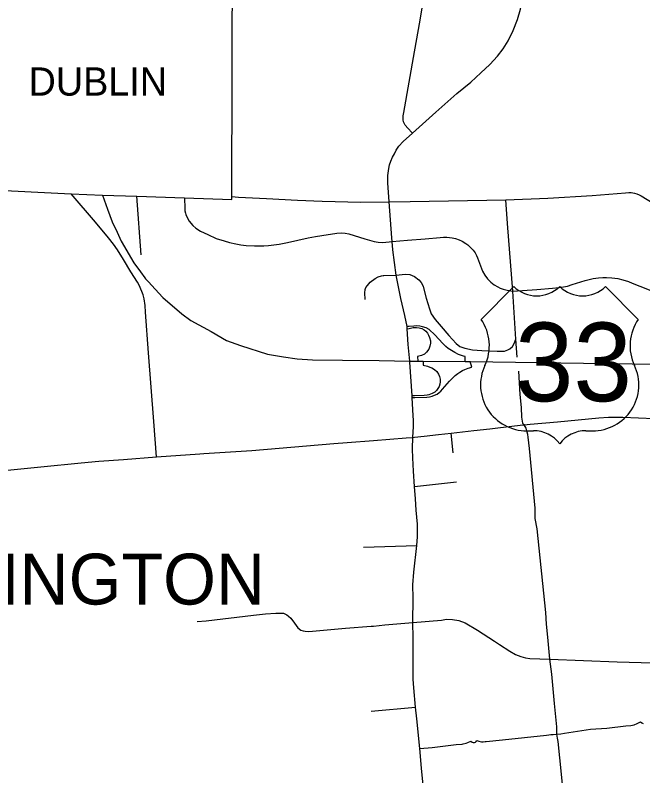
# Model space of a CAD drawing. Extents: x 1755200 to 1902939, y 644115 to 788070.
# Drawn here: x 1777186 to 1788296, y 757899 to 771361 of the extents above; entities that cross this region are included whole.
import ezdxf

# ---------------------------------------------------------------- set-up
doc = ezdxf.new("R2010")
doc.units = 0
for name, color, linetype in [('GM_X_City_Street', 7, 'Continuous'), ('GM_X_Corporation_Text', 7, 'Continuous'), ('GM_X_County', 7, 'Continuous'), ('GM_X_County_Road', 7, 'Continuous'), ('GM_X_Interchange_Ramps', 7, 'Continuous'), ('GM_X_Township_Text', 7, 'Continuous'), ('GM_X_US_Route', 7, 'Continuous'), ('GM_X_US_Shield', 7, 'Continuous')]:
    doc.layers.add(name, color=color, linetype=linetype)

msp = doc.modelspace()

# ---------------------------------------------------------------- linework, layer by layer
at = {"layer": 'GM_X_City_Street'}
for points in [[(1784219, 769275), (1784630, 769643), (1785003, 769974), (1785250, 770175), (1785431, 770342), (1785586, 770486), (1785725, 770636), (1785822, 770764), (1785915, 770909), (1786003, 771088), (1786080, 771284), (1786130, 771467), (1786180, 771733), (1786271, 772205), (1786359, 772769), (1786375, 772928), (1786368, 773096), (1786350, 773256), (1786330, 773355)], [(1784213, 769281), (1784139, 769359), (1784090, 769415), (1784062, 769474), (1784054, 769512), (1784054, 769579), (1784065, 769640), (1784254, 770715), (1784357, 771275), (1784523, 772309), (1784617, 772879)], [(1783804, 768056), (1783780, 768394), (1783780, 768450), (1783783, 768525), (1783798, 768648), (1783813, 768714), (1783836, 768775), (1783866, 768846), (1783898, 768910), (1783928, 768970), (1783978, 769042), (1784055, 769126), (1784219, 769275), (1784213, 769281)], [(1779493, 766103), (1779484, 766221), (1779471, 766340), (1779453, 766411), (1779385, 766572), (1779352, 766635), (1779235, 766821), (1779105, 767038), (1778997, 767211), (1778926, 767307), (1778839, 767419), (1778606, 767697), (1778179, 768197)], [(1781021, 768152), (1781136, 768138), (1781634, 768114), (1782186, 768090), (1782622, 768070), (1783303, 768053), (1783804, 768056), (1784178, 768065), (1785871, 768094), (1786614, 768122), (1787402, 768168), (1787989, 768220), (1788050, 768225), (1788088, 768222), (1788147, 768214), (1788188, 768200), (1788232, 768182), (1788269, 768163), (1789144, 767627)], [(1779414, 767119), (1779340, 768157)], [(1780182, 768130), (1780186, 767940), (1780191, 767900), (1780199, 767860), (1780209, 767831), (1780225, 767791), (1780264, 767716), (1780328, 767640), (1780383, 767593), (1780464, 767541), (1780593, 767477), (1780746, 767411), (1780882, 767365), (1780980, 767338), (1781089, 767315), (1781178, 767298), (1781275, 767287), (1781420, 767277), (1781586, 767278), (1781671, 767283), (1781767, 767294), (1781857, 767309), (1782004, 767339), (1782372, 767420), (1782502, 767447), (1782613, 767464), (1782882, 767503), (1782970, 767511), (1783029, 767506), (1783091, 767492), (1783376, 767405), (1783539, 767357), (1783614, 767345), (1783692, 767340), (1783857, 767355)], [(1783852, 767420), (1783804, 768056)], [(1786072, 765306), (1786049, 765627), (1785994, 766475), (1785901, 767676), (1785871, 768094)], [(1784124, 765809), (1784124, 765849), (1784086, 766044), (1784010, 766349), (1783927, 766762), (1783870, 767211), (1783857, 767355), (1783852, 767420)], [(1783857, 767355), (1784133, 767378), (1784442, 767403), (1784707, 767426), (1784770, 767430), (1784829, 767433), (1784875, 767429), (1784924, 767421), (1784983, 767408), (1785048, 767383), (1785097, 767361), (1785164, 767319), (1785196, 767295), (1785235, 767263), (1785294, 767200), (1785327, 767154), (1785353, 767109), (1785372, 767066), (1785457, 766832), (1785497, 766760), (1785547, 766692), (1785604, 766637), (1785664, 766590), (1785727, 766554), (1785772, 766532), (1785825, 766512), (1785893, 766493), (1785994, 766475)], [(1783380, 766332), (1783377, 766447), (1783380, 766504), (1783395, 766540), (1783423, 766579), (1783467, 766638), (1783560, 766703), (1783610, 766729), (1783668, 766747), (1783699, 766752)], [(1783699, 766752), (1783711, 766754), (1783927, 766762)], [(1783927, 766762), (1784087, 766780), (1784169, 766769), (1784254, 766735), (1784329, 766680), (1784371, 766630)], [(1785994, 766475), (1786422, 766506), (1786697, 766528), (1786810, 766539), (1786893, 766552), (1786966, 766568), (1787044, 766592), (1787277, 766667), (1787418, 766703), (1787513, 766714), (1787587, 766718), (1787656, 766721), (1787746, 766714), (1787852, 766701), (1787940, 766680), (1788043, 766647), (1788107, 766621), (1788242, 766568), (1788469, 766478)], [(1784371, 766630), (1784376, 766624), (1784408, 766561), (1784463, 766354), (1784518, 766165), (1784550, 766075), (1784618, 765975), (1784726, 765853), (1784860, 765691), (1784992, 765549), (1785058, 765499), (1785146, 765465), (1785280, 765436), (1785444, 765424), (1785717, 765413), (1785849, 765415), (1785906, 765439), (1785943, 765457), (1785988, 765495), (1786021, 765551), (1786049, 765627)], [(1779685, 763542), (1779637, 764172), (1779545, 765387), (1779493, 766103)], [(1784171, 765217), (1784170, 765235), (1784144, 765530), (1784124, 765809)], [(1784233, 764269), (1784215, 764596), (1784214, 764625), (1784171, 765217)], [(1786194, 764108), (1786181, 764123), (1786174, 764142), (1786157, 764248), (1786146, 764419), (1786127, 764649), (1786100, 765059)], [(1784229, 763410), (1784229, 763419), (1784225, 763513), (1784220, 763690), (1784225, 763888), (1784235, 764083), (1784237, 764194), (1784233, 764269)], [(1786194, 764108), (1786301, 764120), (1786784, 764165), (1787517, 764236), (1787687, 764247), (1787940, 764244), (1788496, 764220), (1788942, 764207)], [(1784256, 763891), (1784428, 763910), (1784682, 763942), (1784901, 763964), (1785303, 764011), (1785590, 764041), (1785732, 764058), (1786128, 764102), (1786194, 764108)], [(1786891, 757566), (1786854, 757927), (1786800, 758507), (1786789, 758566), (1786774, 758633), (1786775, 758765), (1786733, 759178), (1786683, 759695), (1786650, 759962), (1786616, 760352), (1786592, 760584), (1786580, 760788), (1786424, 762272), (1786390, 762450), (1786389, 762635), (1786289, 763689), (1786266, 763891), (1786259, 763942), (1786246, 764003), (1786230, 764049), (1786194, 764108)], [(1780526, 763602), (1781375, 763657), (1782825, 763782), (1783060, 763799), (1783527, 763834), (1784109, 763878), (1784225, 763888), (1784256, 763891)], [(1784937, 763614), (1784901, 763964)], [(1779104, 763498), (1779685, 763542), (1780457, 763598), (1780526, 763602)], [(1784431, 757489), (1784381, 758034), (1784347, 758381), (1784296, 758904), (1784274, 759116), (1784240, 759453), (1784230, 759608), (1784232, 759677), (1784229, 760052), (1784230, 760338), (1784227, 760609), (1784231, 761045), (1784227, 761277), (1784240, 761501), (1784293, 761975), (1784305, 762129), (1784308, 762257), (1784306, 762353), (1784284, 762601), (1784271, 762802), (1784255, 763022), (1784234, 763291), (1784229, 763410)], [(1784255, 763022), (1784997, 763101)], [(1783351, 761947), (1784293, 761975)], [(1781403, 760741), (1781614, 760766), (1781798, 760777), (1781933, 760777), (1781997, 760747), (1782023, 760726)], [(1780404, 760630), (1780564, 760644), (1781403, 760741)], [(1782023, 760726), (1782065, 760691), (1782129, 760598), (1782192, 760517), (1782245, 760477), (1782283, 760463), (1782319, 760456), (1782381, 760453)], [(1784227, 760609), (1784735, 760656), (1784822, 760669), (1784927, 760665), (1785037, 760648), (1785151, 760606), (1785370, 760479), (1785672, 760283), (1785762, 760223), (1785944, 760103), (1786045, 760047), (1786138, 760011), (1786218, 759985), (1786298, 759975), (1786650, 759962), (1787842, 759914), (1788482, 759895)], [(1782381, 760453), (1782386, 760453), (1783031, 760512), (1783489, 760546)], [(1783489, 760546), (1783531, 760549), (1783727, 760569), (1784227, 760609)], [(1783488, 759043), (1784274, 759116)], [(1785443, 758502), (1785447, 758501), (1785472, 758500), (1785504, 758503), (1785525, 758504), (1785812, 758536), (1786594, 758619), (1786632, 758624), (1786670, 758627), (1786708, 758629), (1786774, 758633), (1786846, 758644), (1786908, 758654), (1787368, 758722), (1787661, 758743), (1787994, 758780), (1788083, 758790), (1788142, 758802), (1788198, 758823), (1788258, 758854), (1788279, 758834), (1788304, 758825)], [(1785099, 758461), (1785117, 758463), (1785168, 758475), (1785196, 758486), (1785249, 758513), (1785274, 758493), (1785296, 758489), (1785314, 758489), (1785332, 758496), (1785348, 758508), (1785360, 758524), (1785395, 758514), (1785443, 758502)], [(1784347, 758381), (1784569, 758402), (1784992, 758452), (1785099, 758461)]]:
    msp.add_lwpolyline(points, dxfattribs=at)
at = {"layer": 'GM_X_County'}
msp.add_lwpolyline([(1775112, 768352), (1778179, 768197), (1778733, 768178), (1779340, 768157), (1780182, 768130), (1781021, 768101), (1781021, 768152), (1781038, 774723)], dxfattribs=at)
at = {"layer": 'GM_X_County_Road'}
msp.add_lwpolyline([(1776312, 763238), (1776864, 763293), (1777637, 763368), (1778352, 763436), (1778667, 763465), (1779104, 763498)], dxfattribs=at)
at = {"layer": 'GM_X_Interchange_Ramps'}
for points in [[(1785153, 765233), (1785154, 765320), (1785124, 765326), (1785036, 765358), (1784970, 765390), (1784907, 765424), (1784851, 765461), (1784810, 765495), (1784755, 765549), (1784613, 765705), (1784512, 765799), (1784462, 765826), (1784398, 765848), (1784348, 765859), (1784295, 765863), (1784240, 765858), (1784159, 765854), (1784124, 765849)], [(1784124, 765809), (1784161, 765815), (1784230, 765832), (1784292, 765836), (1784340, 765828), (1784382, 765814), (1784423, 765791), (1784453, 765767), (1784482, 765734), (1784505, 765698), (1784522, 765654), (1784536, 765596), (1784538, 765557), (1784528, 765501), (1784506, 765449), (1784469, 765398), (1784430, 765363), (1784381, 765338), (1784309, 765320), (1784313, 765239)], [(1784407, 765240), (1784406, 765164), (1784482, 765148), (1784524, 765134), (1784564, 765117), (1784608, 765091), (1784651, 765052), (1784680, 765010), (1784696, 764968), (1784709, 764918), (1784709, 764871), (1784702, 764833), (1784689, 764792), (1784670, 764756), (1784642, 764719), (1784614, 764691), (1784570, 764665), (1784539, 764652), (1784506, 764641), (1784479, 764636), (1784426, 764632), (1784254, 764626), (1784214, 764625)], [(1784215, 764596), (1784263, 764593), (1784470, 764602), (1784518, 764608), (1784567, 764617), (1784610, 764633), (1784654, 764656), (1784690, 764681), (1784722, 764709), (1784752, 764740), (1784875, 764884), (1784926, 764939), (1784976, 764983), (1785023, 765019), (1785056, 765043), (1785106, 765071), (1785147, 765091), (1785206, 765113), (1785270, 765131), (1785239, 765232)]]:
    msp.add_lwpolyline(points, dxfattribs=at)
at = {"layer": 'GM_X_US_Route'}
for points in [[(1778733, 768178), (1778817, 767930), (1778905, 767705), (1778988, 767518), (1779062, 767362), (1779287, 766981), (1779404, 766816), (1779481, 766710)], [(1779481, 766710), (1779494, 766693), (1779551, 766633)], [(1779551, 766633), (1779597, 766584), (1779797, 766367), (1780136, 766075), (1780293, 765955), (1780653, 765760), (1780928, 765603), (1781172, 765512), (1781651, 765359), (1781933, 765316), (1782177, 765280), (1782448, 765261), (1782979, 765256)], [(1782979, 765256), (1783630, 765249), (1784170, 765235)], [(1784170, 765235), (1784313, 765239), (1784407, 765240), (1785153, 765233), (1785239, 765232), (1787647, 765195), (1789027, 765180), (1789601, 765171), (1789778, 765169)]]:
    msp.add_lwpolyline(points, dxfattribs=at)
at = {"layer": 'GM_X_US_Shield'}
for p, q in [((1786013, 766558), (1785433, 765978)), ((1788217, 765978), (1787637, 766558)), ((1786245, 764006), (1786361, 764006)), ((1787289, 764006), (1787405, 764006))]:
    msp.add_line(p, q, dxfattribs=at)
for centre, radius, start, end in [((1786419, 766973), 580, 225.573, 314.427), ((1787231, 766973), 580, 225.573, 314.427), ((1784768, 765512), 812, 334.5471, 35.0009), ((1788882, 765512), 812, 144.9991, 205.4529), ((1786236, 764818), 812, 154.8319, 270.6383), ((1787414, 764818), 812, 269.3617, 25.1681), ((1786361, 763426), 580, 36.8699, 90), ((1787289, 763426), 580, 90, 143.1301)]:
    msp.add_arc(centre, radius, start, end, dxfattribs=at)

# ---------------------------------------------------------------- texts
at = {"layer": 'GM_X_Corporation_Text'}
msp.add_text('DUBLIN', height=500, rotation=0, dxfattribs=at).set_placement((1777422, 769938))
at = {"layer": 'GM_X_Township_Text'}
msp.add_text('WASHINGTON', height=900, rotation=0, dxfattribs=at).set_placement((1773318, 760930))
at = {"layer": 'GM_X_US_Shield'}
msp.add_text('33', height=1392.2, dxfattribs=at).set_placement((1786033, 764528))

doc.saveas('drawing.dxf')
